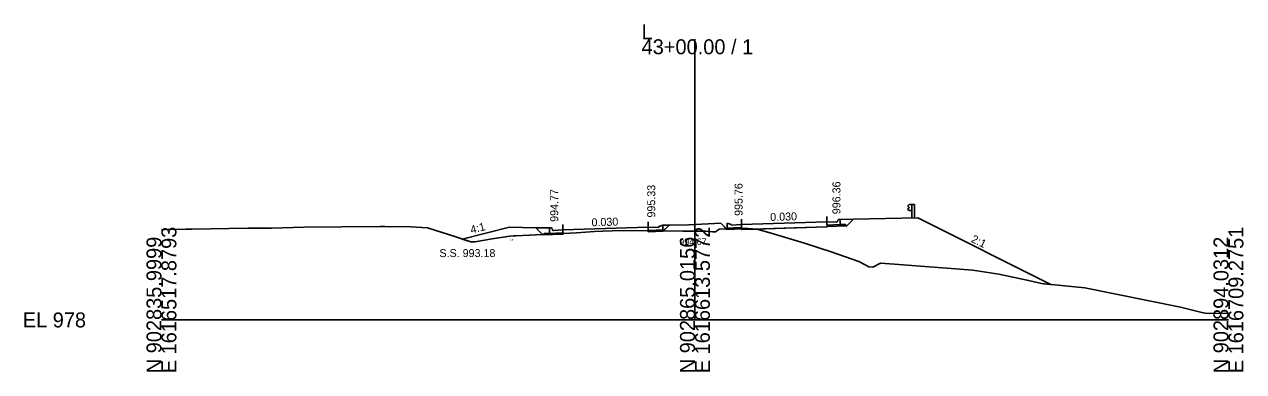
# Model space of a CAD drawing. Extents: x 1009 to 7438, y -1586 to 7964.
# Drawn here: x 4009.2 to 4237.7, y 914 to 979.2 of the extents above; entities that cross this region are included whole.
import ezdxf

# ---------------------------------------------------------------- set-up
doc = ezdxf.new("R2010")
doc.units = 0
for name, color, linetype in [('Exist Cross Section Cell', 7, 'Continuous'), ('Exist XS Center Line Elevation Label', 7, 'Continuous'), ('Exist XS Ground Line', 7, 'Continuous'), ('Prop XS Dump Level', 7, 'Continuous'), ('Prop XS Earthwork Shape', 7, 'Continuous'), ('Prop XS EOT Tick Mark', 7, 'Continuous'), ('Prop XS Finish Grade', 7, 'Continuous'), ('Prop XS Finish Grade CurbGutter', 7, 'Continuous'), ('Prop XS Finish Grade Earthwork', 7, 'Continuous'), ('Prop XS Finish Grade Pavement', 7, 'Continuous'), ('Prop XS Guardrail', 7, 'Continuous'), ('Prop XS Hydro Elevations', 7, 'Continuous'), ('Prop XS Pvmt Edge Slope', 7, 'Continuous'), ('Prop XS SE Text', 7, 'Continuous'), ('Prop XS Side Slope Text', 7, 'Continuous'), ('Prop XS SS Elevation Text', 7, 'Continuous'), ('Prop XS Subgrade CurbGutter', 7, 'Continuous'), ('Prop XS Subgrade Earthwork', 7, 'Continuous')]:
    doc.layers.add(name, color=color, linetype=linetype)

msp = doc.modelspace()

# ---------------------------------------------------------------- linework, layer by layer
at = {"layer": 'Exist Cross Section Cell'}
for p, q in [((4134.89, 923.73), (4134.89, 976.36)), ((4034.89, 923.73), (4134.89, 923.73)), ((4134.89, 923.73), (4234.89, 923.73))]:
    msp.add_line(p, q, dxfattribs=at)
at = {"layer": 'Exist XS Ground Line'}
for p, q in [((4034.89, 940.66), (4035.59, 940.67)), ((4035.59, 940.67), (4039.49, 940.74)), ((4039.49, 940.74), (4040.67, 940.75)), ((4040.67, 940.75), (4047.5, 940.85)), ((4047.5, 940.85), (4051.12, 940.92)), ((4051.12, 940.92), (4055.52, 940.94)), ((4055.52, 940.94), (4061.57, 941.1)), ((4061.57, 941.1), (4075.83, 941.26)), ((4075.83, 941.26), (4076.76, 941.27)), ((4076.76, 941.27), (4081.65, 941.22)), ((4081.65, 941.22), (4084.79, 941.03)), ((4084.79, 941.03), (4090.07, 939.29)), ((4090.07, 939.29), (4092.88, 938.37)), ((4096.88, 938.93), (4100.19, 939.43)), ((4100.19, 939.43), (4100.88, 939.49)), ((4100.88, 939.49), (4101.29, 939.53)), ((4101.29, 939.53), (4108.96, 939.89)), ((4108.96, 939.89), (4112.7, 940.07)), ((4112.7, 940.07), (4116.07, 940.3)), ((4116.07, 940.3), (4117.61, 940.41)), ((4117.61, 940.41), (4119.35, 940.45)), ((4119.35, 940.45), (4122.8, 940.51)), ((4122.8, 940.51), (4132.59, 940.41)), ((4132.59, 940.41), (4134.89, 940.4)), ((4134.89, 940.4), (4136.9, 940.38)), ((4136.9, 940.38), (4138.2, 940.28)), ((4138.2, 940.28), (4138.74, 940.26)), ((4138.74, 940.26), (4139.41, 940.78)), ((4139.41, 940.78), (4142.87, 940.88)), ((4142.87, 940.88), (4144.35, 940.92)), ((4144.35, 940.92), (4144.86, 940.87)), ((4144.86, 940.87), (4146.47, 940.77)), ((4146.47, 940.77), (4149.17, 939.99)), ((4149.17, 939.99), (4155.4, 938.16)), ((4092.88, 938.37), (4093.63, 938.37)), ((4093.63, 938.37), (4096.88, 938.93)), ((4155.4, 938.16), (4160.4, 936.48)), ((4160.4, 936.48), (4165.59, 934.72)), ((4165.59, 934.72), (4166.79, 934.07)), ((4166.79, 934.07), (4167.47, 933.66)), ((4167.47, 933.66), (4168.23, 933.65)), ((4168.23, 933.65), (4169.66, 934.38)), ((4169.66, 934.38), (4172.27, 934.22)), ((4172.27, 934.22), (4186.97, 933.06)), ((4186.97, 933.06), (4191.84, 932.29)), ((4191.84, 932.29), (4197.42, 931.14)), ((4197.42, 931.14), (4199.86, 930.58)), ((4199.86, 930.58), (4207.97, 929.76)), ((4207.97, 929.76), (4225.93, 926.14)), ((4225.93, 926.14), (4229.88, 925.13)), ((4229.88, 925.13), (4230.53, 924.98)), ((4230.53, 924.98), (4231.25, 924.96)), ((4231.25, 924.96), (4234.54, 924.97)), ((4234.54, 924.97), (4234.89, 924.95))]:
    msp.add_line(p, q, dxfattribs=at)
at = {"layer": 'Prop XS Dump Level'}
for p, q in [((4143.64, 941.62), (4159.64, 942.1)), ((4143.64, 941.62), (4159.64, 942.1)), ((4110.14, 940.62), (4126.14, 941.1)), ((4110.14, 940.62), (4126.14, 941.1))]:
    msp.add_line(p, q, dxfattribs=at)
at = {"layer": 'Prop XS Earthwork Shape'}
for points in [[(4128.99, 940.45), (4132.59, 940.41), (4134.89, 940.4), (4136.9, 940.38), (4138.2, 940.28), (4138.74, 940.26), (4139.41, 940.78), (4140.78, 940.82), (4139.74, 941.85), (4133.76, 941.58), (4130.27, 941.51), (4130.04, 941.5)], [(4160.4, 936.48), (4165.59, 934.72), (4166.79, 934.07), (4167.47, 933.66), (4168.23, 933.65), (4169.66, 934.38), (4172.27, 934.22), (4186.97, 933.06), (4191.84, 932.29), (4197.42, 931.14), (4199.86, 930.58), (4200.3, 930.53), (4201.6, 930.4), (4176.64, 942.88), (4164.64, 942.64), (4163.39, 941.38), (4159.64, 941.27), (4159.64, 941.19), (4146.2, 940.78), (4146.47, 940.77), (4149.17, 939.99), (4155.4, 938.16)], [(4100.88, 939.49), (4101.29, 939.53), (4106.3, 939.76), (4105.04, 941.03), (4100.14, 941.14), (4091.23, 938.91), (4092.88, 938.37), (4093.63, 938.37), (4096.88, 938.93), (4100.19, 939.43)], [(4106.3, 939.76), (4106.49, 939.77), (4106.39, 939.67)], [(4106.49, 939.77), (4106.39, 939.67), (4110.14, 939.79), (4110.14, 939.95), (4108.96, 939.89)], [(4128.78, 940.45), (4128.89, 940.35), (4126.14, 940.27), (4126.14, 940.48)], [(4128.78, 940.45), (4128.89, 940.35), (4128.99, 940.45)], [(4140.88, 940.71), (4140.78, 940.82), (4141, 940.82)], [(4142.87, 940.88), (4144.35, 940.92), (4144.86, 940.87), (4146.2, 940.78), (4143.64, 940.71), (4143.64, 940.79), (4140.88, 940.71), (4141, 940.82)]]:
    msp.add_lwpolyline(points, close=True, dxfattribs=at)
at = {"layer": 'Prop XS EOT Tick Mark'}
for p, q in [((4110.14, 940.62), (4110.14, 941.62)), ((4126.14, 941.1), (4126.14, 942.1)), ((4143.64, 941.62), (4143.64, 942.62)), ((4159.64, 942.1), (4159.64, 943.1))]:
    msp.add_line(p, q, dxfattribs=at)
at = {"layer": 'Prop XS Finish Grade'}
for p, q in [((4162.14, 942.58), (4164.64, 942.64)), ((4107.64, 940.98), (4105.04, 941.03)), ((4128.89, 941.48), (4130.04, 941.5))]:
    msp.add_line(p, q, dxfattribs=at)
at = {"layer": 'Prop XS Finish Grade CurbGutter'}
for p, q in [((4141.65, 941.65), (4140.9, 941.9)), ((4141.65, 941.48), (4141.65, 941.65)), ((4143.64, 941.62), (4141.65, 941.48)), ((4143.64, 941.62), (4142.89, 941.57)), ((4159.64, 942.1), (4161.39, 942.08)), ((4161.39, 942.08), (4161.52, 942.11)), ((4161.52, 942.11), (4161.61, 942.2)), ((4161.61, 942.2), (4161.68, 942.45)), ((4161.68, 942.45), (4161.77, 942.54)), ((4161.89, 942.58), (4161.77, 942.54)), ((4162.14, 942.58), (4161.89, 942.58)), ((4107.64, 940.98), (4107.89, 940.98)), ((4107.89, 940.98), (4108.02, 940.95)), ((4108.11, 940.86), (4108.02, 940.95)), ((4108.18, 940.61), (4108.11, 940.86)), ((4108.27, 940.52), (4108.18, 940.61)), ((4108.39, 940.49), (4108.27, 940.52)), ((4110.14, 940.62), (4108.39, 940.49)), ((4126.14, 941.1), (4128.14, 941.06)), ((4128.14, 941.23), (4128.89, 941.48)), ((4128.14, 941.06), (4128.14, 941.23))]:
    msp.add_line(p, q, dxfattribs=at)
at = {"layer": 'Prop XS Finish Grade Earthwork'}
for p, q in [((4130.04, 941.5), (4133.76, 941.58)), ((4139.74, 941.85), (4133.76, 941.58)), ((4164.64, 942.64), (4176.64, 942.88)), ((4176.64, 942.88), (4201.6, 930.4)), ((4100.14, 941.14), (4091.23, 938.91)), ((4105.04, 941.03), (4100.14, 941.14))]:
    msp.add_line(p, q, dxfattribs=at)
at = {"layer": 'Prop XS Finish Grade Pavement'}
for p, q in [((4143.64, 941.62), (4159.64, 942.1)), ((4110.14, 940.62), (4126.14, 941.1))]:
    msp.add_line(p, q, dxfattribs=at)
at = {"layer": 'Prop XS Guardrail'}
for p, q in [((4174.77, 945.16), (4174.74, 945.1)), ((4174.74, 945.1), (4174.77, 945.04)), ((4174.77, 944.55), (4174.74, 944.49)), ((4174.74, 944.49), (4174.77, 944.43)), ((4175.06, 945.36), (4174.77, 945.16)), ((4174.77, 945.04), (4175.06, 944.84)), ((4175.06, 944.75), (4174.77, 944.55)), ((4174.77, 944.43), (4175.06, 944.23)), ((4175.56, 945.36), (4175.06, 945.36)), ((4175.06, 944.84), (4175.06, 944.75)), ((4175.06, 944.23), (4175.56, 944.23)), ((4176.06, 945.36), (4175.56, 945.36)), ((4175.56, 945.36), (4175.56, 942.86)), ((4176.06, 942.86), (4176.06, 945.36))]:
    msp.add_line(p, q, dxfattribs=at)
at = {"layer": 'Prop XS Pvmt Edge Slope'}
for p, q in [((4162.14, 941.6), (4163.14, 941.63)), ((4163.14, 941.63), (4163.39, 941.38)), ((4106.64, 939.93), (4106.39, 939.67)), ((4107.64, 939.96), (4106.64, 939.93)), ((4127.64, 940.55), (4128.89, 940.57)), ((4128.67, 940.57), (4128.89, 940.35)), ((4141.14, 940.97), (4140.88, 940.71)), ((4142.14, 941), (4140.9, 940.96))]:
    msp.add_line(p, q, dxfattribs=at)
at = {"layer": 'Prop XS Subgrade CurbGutter'}
for p, q in [((4140.9, 940.96), (4140.9, 941.9)), ((4143.64, 941.62), (4143.64, 941.04)), ((4159.64, 942.1), (4159.64, 941.52)), ((4159.64, 941.52), (4162.14, 941.6)), ((4162.14, 941.6), (4162.14, 942.58)), ((4107.64, 939.96), (4107.64, 940.98)), ((4110.14, 940.04), (4107.64, 939.96)), ((4110.14, 940.62), (4110.14, 940.04)), ((4126.14, 941.1), (4126.14, 940.52)), ((4126.14, 940.52), (4127.64, 940.55)), ((4128.89, 940.57), (4128.89, 941.48)), ((4143.64, 941.04), (4142.14, 941))]:
    msp.add_line(p, q, dxfattribs=at)
at = {"layer": 'Prop XS Subgrade Earthwork'}
for p, q in [((4140.88, 940.71), (4139.74, 941.85)), ((4163.39, 941.38), (4164.64, 942.64)), ((4106.39, 939.67), (4105.04, 941.03)), ((4110.14, 939.79), (4106.39, 939.67)), ((4110.14, 939.79), (4110.14, 939.95)), ((4126.14, 940.27), (4126.14, 940.48)), ((4126.14, 940.27), (4128.89, 940.35)), ((4128.89, 940.35), (4130.04, 941.5)), ((4143.64, 940.79), (4140.88, 940.71)), ((4143.64, 940.71), (4159.64, 941.19)), ((4143.64, 940.71), (4143.64, 940.79)), ((4159.64, 941.27), (4163.39, 941.38)), ((4159.64, 941.19), (4159.64, 941.27))]:
    msp.add_line(p, q, dxfattribs=at)

# ---------------------------------------------------------------- texts
at = {"layer": 'Exist Cross Section Cell'}
for s, p in [('L', (4124.89, 976.36)), ('43+00.00 / 1', (4124.89, 973.56)), ('EL 978', (4008.89, 922.33))]:
    msp.add_text(s, height=2.8, dxfattribs=at).set_placement(p)
for s, p in [('E 1616517.8793', (4037.69, 913.73)), ('E 1616613.5772', (4137.69, 913.73)), ('E 1616709.2751', (4237.69, 913.73)), ('N 902835.9999', (4034.89, 913.73)), ('N 902865.0156', (4134.89, 913.73)), ('N 902894.0312', (4234.89, 913.73))]:
    msp.add_text(s, height=2.8, rotation=90, dxfattribs=at).set_placement(p)
at = {"layer": 'Exist XS Center Line Elevation Label'}
msp.add_text('994.67', height=1.25, dxfattribs=at).set_placement((4131.96, 937.77))
at = {"layer": 'Prop XS Dump Level'}
for p in [(4136.9, 939.64), (4136.9, 939.64), (4136.9, 939.64), (4100.21, 938.69)]:
    msp.add_text('Eop', height=0.3, dxfattribs=at).set_placement(p)
at = {"layer": 'Prop XS Hydro Elevations'}
for s, p in [('995.33', (4127.45, 942.94)), ('995.76', (4143.82, 943.24)), ('996.36', (4162.16, 943.56)), ('994.77', (4109.26, 942.13))]:
    msp.add_text(s, height=1.5, rotation=90, dxfattribs=at).set_placement(p)
at = {"layer": 'Prop XS SE Text'}
for p in [(4149.02, 942.28), (4115.52, 941.28)]:
    msp.add_text('0.030', height=1.5, rotation=1.7184, dxfattribs=at).set_placement(p)
at = {"layer": 'Prop XS Side Slope Text'}
for s, rotation, p in [('4:1', 14.0362, (4093, 939.9)), ('2:1', 333.4349, (4186.53, 938.43))]:
    msp.add_text(s, height=1.5, rotation=rotation, dxfattribs=at).set_placement(p)
at = {"layer": 'Prop XS SS Elevation Text'}
msp.add_text('S.S. 993.18', height=1.5, dxfattribs=at).set_placement((4087, 935.52))

doc.saveas('drawing.dxf')
